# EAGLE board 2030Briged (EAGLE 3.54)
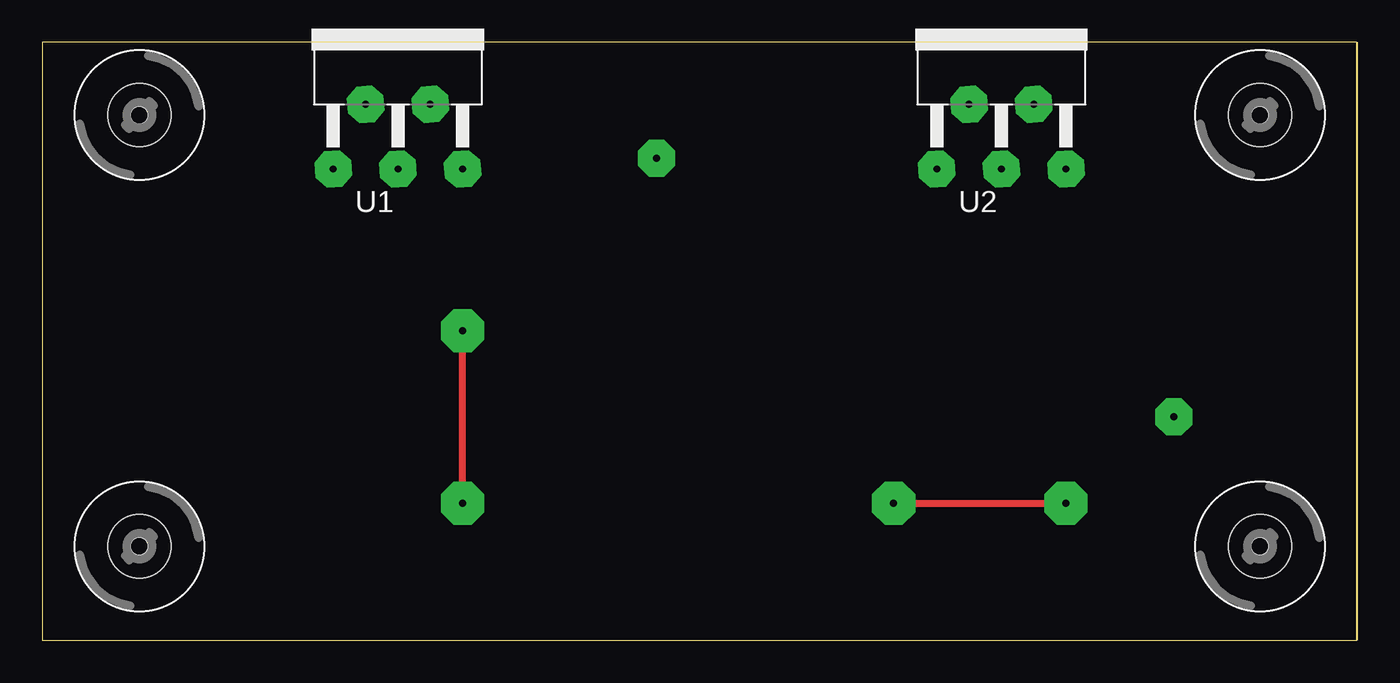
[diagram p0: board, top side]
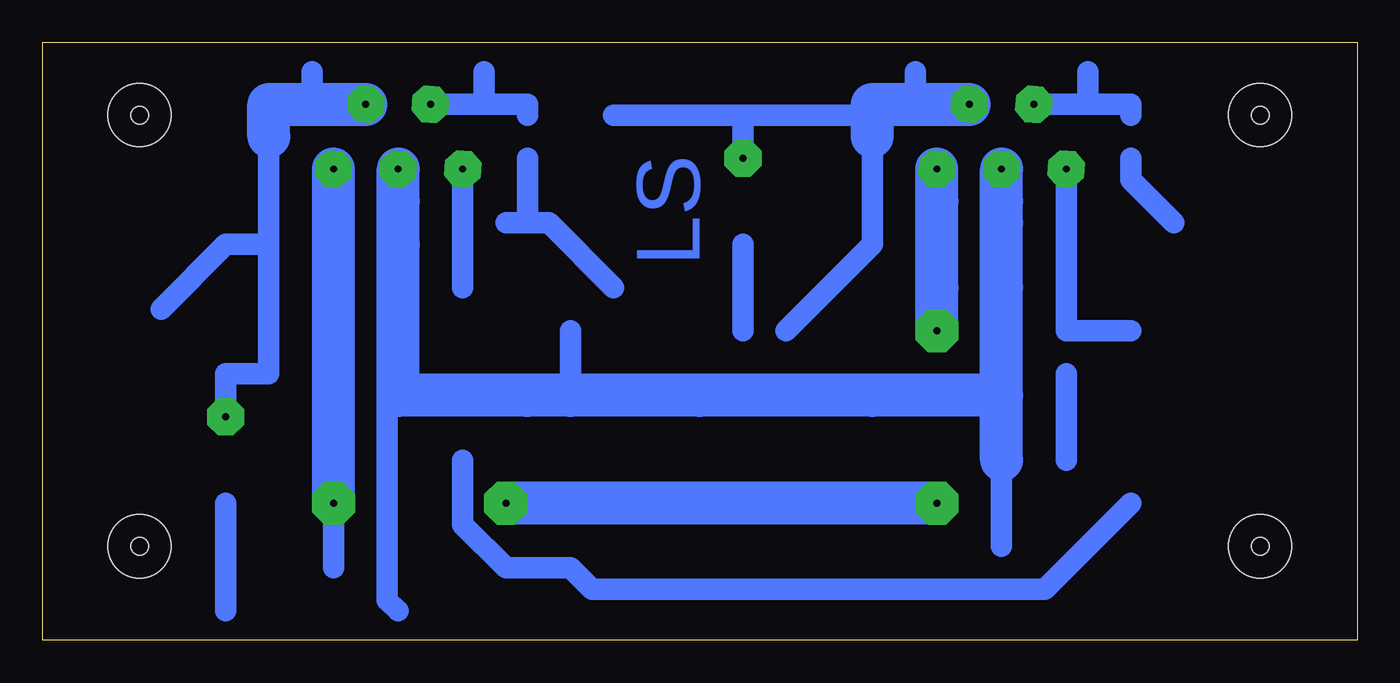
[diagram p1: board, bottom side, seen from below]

Size 77.47 x 35.23 mm. Coordinates in mm from the lower left corner, seen from the top.
Outline: 77.47,35.23 77.47,0
Outline: 0,0 77.45,0 77.45,35.23 0,35.23 0,0
Copper layers used: Top, Bottom

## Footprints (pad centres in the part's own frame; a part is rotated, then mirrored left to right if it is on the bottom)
360 = drill 0.406 pad 2.159 octagon:  -3.81,-8.255;  -1.905,-4.445;  0,-8.255;  1.905,-4.445;  3.81,-8.255
IL-3,5 = hole 3.708: 0,0 | hole 1.016: 0,0

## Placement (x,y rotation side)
C1  1æ  [-2,5L]  17.14,18.25 270 top
C2  100æ  [-2,5L]  20.95,3.01 90 top
C3  22æ  [-2,5L]  13.33,30.95 270 top
C4  47n  [2,5]  58.41,25.87 0 top
C5  100æ  [-2,5L]  59.69,14.44 180 top
C6  0,22æ  [7,5]  36.19,27.14 90 top
C7  47n  [2,5]  22.86,25.87 0 top
C8  100æ  [-2,5L]  24.12,20.79 180 top
C9  0,22æ  [7,5]  66.67,11.9 90 top
C10  22æ  [-2,5L]  48.89,30.95 270 top
D1  1N4001  [10]  28.57,19.52 90 top
D2  1N4001  [10]  61.59,23.33 0 top
D3  1N4001  [10]  65.4,19.52 180 top
D4  1N4001  [10]  33.65,13.17 270 top
GND  GND  [D]  38.73,14.44 0 top
IN+  PAD  [D]  17.14,10.63 0 top
IN-  PAD  [D]  20.95,10.63 0 top
OUT+  PAD  [D]  28.57,29.68 0 top
OUT-  PAD  [D]  64.13,29.68 0 top
R1  22k  [10]  55.24,4.28 0 top
R2  22k  [10]  46.35,9.36 270 top
R3  22k  [10]  13.33,13.17 90 top
R4  680  [10]  15.87,24.6 180 top
R5  22k  [10]  20.95,33.49 0 top
R6  1  [10]  41.27,18.25 180 top
R7  1  [10]  61.59,1.74 0 top
R8  22k  [10]  56.51,33.49 180 top
R9  680  [10]  50.16,19.52 90 top
R10  22k  [10]  52.7,15.71 90 top
R11  22k  [10]  43.81,25.87 90 top
U1  TDA2030V  [360]  20.95,36.03 0 top
U2  TDA2030V  [360]  56.51,36.03 0 top
U$1  [IL-3,5]  5.71,30.95 0 top
U$2  [IL-3,5]  71.75,30.95 0 top
U$3  [IL-3,5]  5.71,5.55 0 top
U$4  [IL-3,5]  71.75,5.55 0 top
VCC  max 35V  [D]  38.73,8.09 0 top

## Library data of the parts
C1-C10 D1-D4 GND IN+ IN- OUT+ OUT- R1-R11 VCC = DISCRETE
U1 U2 = LINEAR
U$1-U$4 = SPECIAL

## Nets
GND: C2. C4. C5. C7. C8. D1. D2. GND. IN-. R2. R4. R6. R7. R9. U1. U2.
N$4: C1. R3. U1.
N$6: C10. R8. U2.
N$7: R10. U2.
N$8: C9. R7.
N$10: C1. IN+.
N$11: C3. R5. U1.
N$13: C3. R4.
N$14: C6. R6.
N$15: C2. R1. R2. R3. R10.
N$16: C10. R9. R11.
N$17: C6. D1. D4. OUT+. R5. R11. U1.
N$18: C9. D2. D3. OUT-. R8. U2.
V+: C4. C5. C7. C8. D3. D4. R1. U1. U2. VCC.

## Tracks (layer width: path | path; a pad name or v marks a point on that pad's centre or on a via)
GND
  Bottom 1.27: 20.95,20.79 21.58,20.79 | 20.95,25.87 21.58,25.87 | 48.89,14.44 50.16,14.44 | 56.51,14.44 57.15,14.44 57.15,2.38 56.51,1.74 | 56.51,25.87 57.15,25.87 | 46.35,14.44 46.35,18.25 | 20.95,5.55 20.95,10.63
  Bottom 2.54: 20.95,14.44 28.57,14.44 38.73,14.44 46.35,14.44 48.89,14.44 56.51,14.44 56.51,23.33 56.51,25.87 56.51,27.77 | 20.95,14.44 20.95,20.79 20.95,24.6 20.95,25.87 20.95,27.77 | 20.95,10.63 20.95,14.44
N$3  (via drill 0.61 pad 2.54)
  other vias: 5.71,30.95
N$4
  Bottom 1.27: 17.14,27.77 17.14,18.25 13.33,18.25
N$5  (via drill 0.61 pad 2.54)
  other vias: 5.71,5.55
N$6
  Bottom 1.27: 51.43,31.58 54.61,31.58 | 51.43,31.58 51.43,33.49 | 51.43,31.58 48.89,31.58 48.89,30.95
N$7
  Bottom 1.27: 52.7,20.79 52.7,27.77
N$8
  Bottom 1.27: 66.67,1.74 66.67,8.09
N$9  (via drill 0.61 pad 2.54)
  other vias: 71.75,5.55
N$10
  Bottom 1.27: 17.14,10.63 17.14,15.71
N$11
  Bottom 1.27: 15.87,31.58 19.04,31.58 | 15.87,31.58 15.87,33.49 | 15.87,31.58 13.33,31.58 13.33,30.95
N$12  (via drill 0.61 pad 2.54)
  other vias: 71.75,30.95
N$13
  Bottom 1.27: 10.79,24.6 13.33,27.14 13.33,28.41
N$14
  Bottom 1.27: 36.19,18.25 36.19,23.33
N$15
  Bottom 1.27: 52.7,10.63 52.7,6.82 50.16,4.28 46.35,4.28 45.08,3.01 20.95,3.01 18.41,3.01 13.33,8.09
N$16
  Bottom 1.27: 48.89,28.41 48.89,24.6 50.16,24.6 47.62,24.6 43.81,20.79
N$17  (via drill 0.41 pad 2.18)
  Bottom 1.27: 28.57,31.58 26.03,31.58 26.03,33.49 | 28.57,29.68 28.57,24.6 28.57,23.33 33.65,18.25 | 36.19,30.95 43.81,30.95 | 28.57,30.95 36.19,30.95 | 36.19,30.95 v36.19,28.41
  Bottom 2.54: 22.86,31.58 28.57,31.58 28.57,30.95 28.57,29.68
N$18  (via drill 0.41 pad 2.18)
  Bottom 1.27: 61.59,33.49 61.59,32.22 64.13,32.22 64.13,29.68 64.13,23.33 | 64.13,23.33 64.13,15.71 66.67,15.71 v66.67,13.17 | 64.13,23.33 66.67,23.33 70.48,19.52
  Bottom 2.54: 58.41,31.58 64.13,31.58 64.13,29.68
V+  (via drill 0.41 pad 2.54)
  Top 0.406: v50.16,8.09 v60.32,8.09 | v24.76,8.09 v24.76,18.25
  Bottom 1.27: 24.76,25.87 24.12,25.87 | 60.32,25.87 59.69,25.87 | 24.76,20.79 24.12,20.79 | 60.32,14.44 59.69,14.44 | v60.32,8.09 60.32,4.28
  Bottom 2.54: U1. 24.76,25.87 24.76,20.79 v24.76,18.25 | U2. 60.32,25.87 60.32,19.52 60.32,14.44 v60.32,8.09 | v50.16,8.09 38.73,8.09 33.65,8.09 v24.76,8.09

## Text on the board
Bottom: LS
